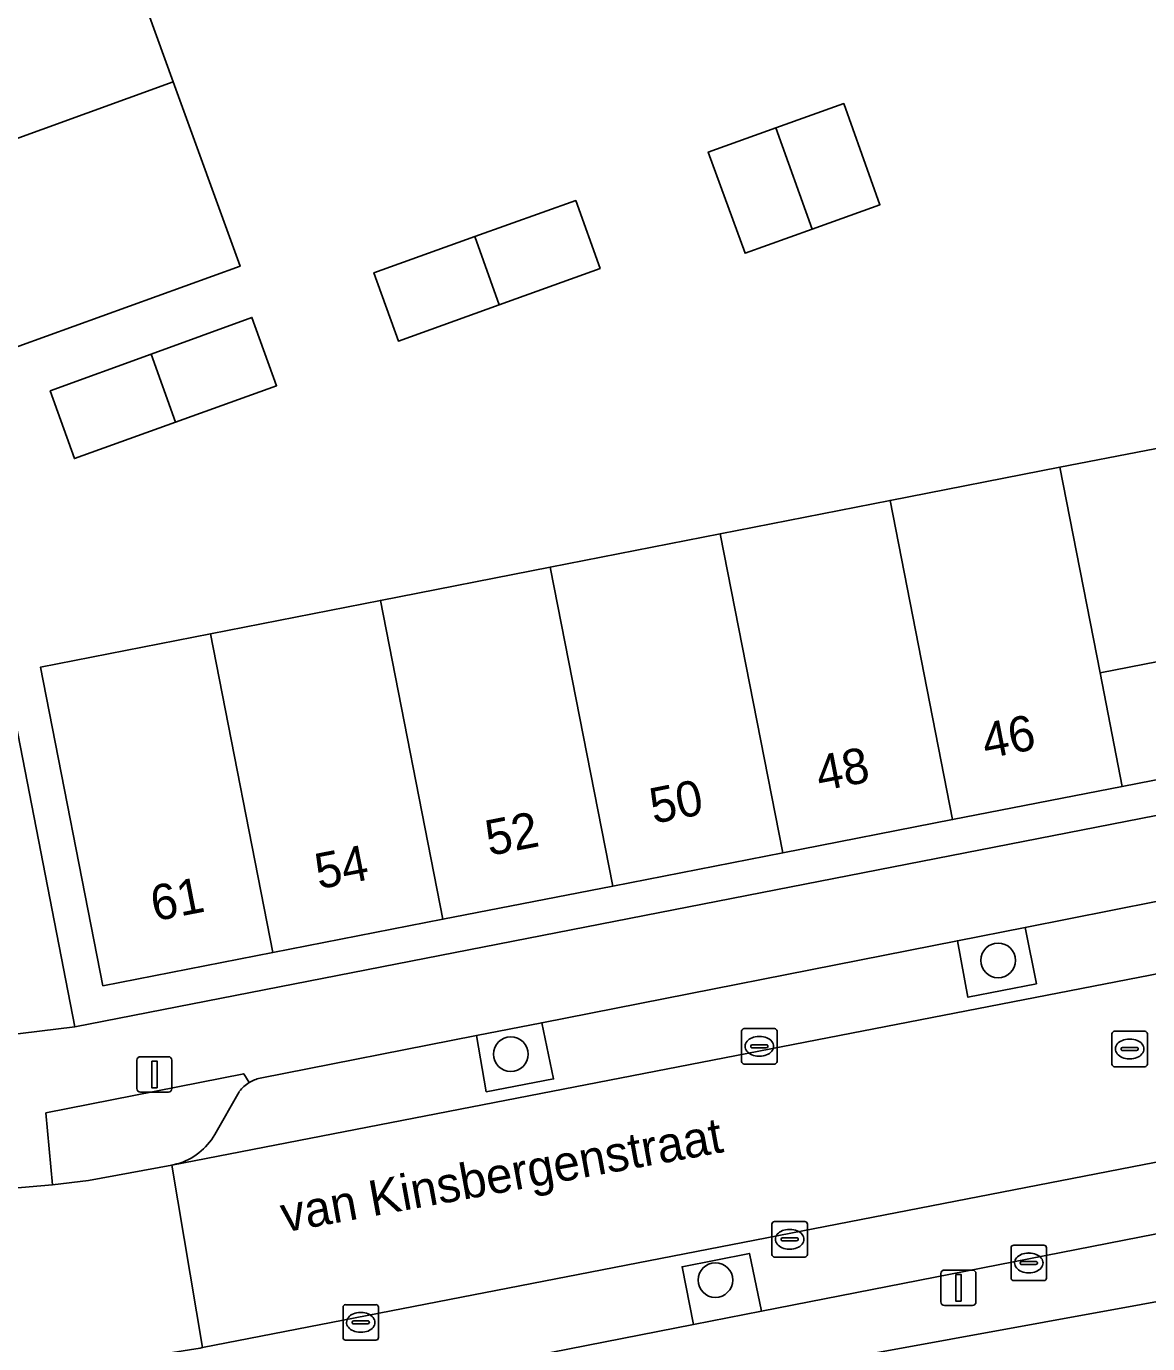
# Model space of a CAD drawing. Extents: x 160377 to 161131, y 383938 to 384853.
# Drawn here: x 160681.61 to 160713.26, y 384498.34 to 384535.5 of the extents above; entities that cross this region are included whole.
import ezdxf

# ---------------------------------------------------------------- set-up
doc = ezdxf.new("R2010")
doc.units = 0
for name, color, linetype in [('IMGEO_Boom', 7, 'Continuous'), ('IMGEO_Drainageput', 7, 'Continuous'), ('IMGEO_Erf', 7, 'Continuous'), ('IMGEO_Groenvoorziening', 7, 'Continuous'), ('IMGEO_Kolk', 7, 'Continuous'), ('IMGEO_Lichtmast', 7, 'Continuous'), ('IMGEO_Openbare_ruimte_label', 7, 'Continuous'), ('IMGEO_Pand', 7, 'Continuous'), ('IMGEO_Pand_nummerreeks', 7, 'Continuous'), ('IMGEO_Pand_overbouw', 7, 'Continuous'), ('IMGEO_Parkeervlak_open', 7, 'Continuous'), ('IMGEO_Rijbaan_lokaal_open', 7, 'Continuous'), ('IMGEO_Rioolput', 7, 'Continuous'), ('IMGEO_Voetgangersgebied_open', 7, 'Continuous'), ('IMGEO_Voetpad_open', 7, 'Continuous')]:
    doc.layers.add(name, color=color, linetype=linetype)

msp = doc.modelspace()

# ---------------------------------------------------------------- linework, layer by layer
at = {"layer": 'IMGEO_Boom'}
for centre in [(160709.037, 384509.154), (160695.282, 384506.508), (160701.057, 384500.136)]:
    msp.add_circle(centre, 0.489, dxfattribs=at)
at = {"layer": 'IMGEO_Drainageput'}
for p, q in [((160709.477, 384501.119), (160710.329, 384501.119)), ((160709.402, 384500.193), (160709.402, 384501.045)), ((160709.89, 384500.899), (160709.915, 384500.899)), ((160710.403, 384501.045), (160710.403, 384500.193)), ((160709.661, 384500.613), (160709.661, 384500.625)), ((160710.099, 384500.576), (160709.701, 384500.576)), ((160709.704, 384500.662), (160710.102, 384500.662)), ((160709.913, 384500.339), (160709.888, 384500.339)), ((160710.145, 384500.625), (160710.145, 384500.613)), ((160710.329, 384500.119), (160709.477, 384500.119))]:
    msp.add_line(p, q, dxfattribs=at)
for points in [[(160709.477, 384501.119), (160710.329, 384501.119)], [(160709.402, 384500.193), (160709.402, 384501.045)], [(160710.403, 384501.045), (160710.403, 384500.193)], [(160710.329, 384500.119), (160709.477, 384500.119)]]:
    msp.add_lwpolyline(points, dxfattribs=at)
for centre, radius, start, end in [((160709.479, 384501.043), 0.0765, 91.552, 178.448), ((160709.479, 384501.043), 0.0765, 91.552, 178.448), ((160710.327, 384501.043), 0.0765, 1.552, 88.448), ((160710.327, 384501.043), 0.0765, 1.552, 88.448), ((160709.701, 384500.622), 0.0403, 85.8775, 175.7526), ((160709.698, 384500.612), 0.0366, 178.938, 274.7102), ((160710.102, 384500.619), 0.043, 264.8664, 352.4533), ((160710.106, 384500.624), 0.0386, 1.7309, 96.639), ((160709.479, 384500.195), 0.0765, 181.552, 268.448), ((160709.479, 384500.195), 0.0765, 181.552, 268.448), ((160710.327, 384500.195), 0.0765, 271.552, 358.448), ((160710.327, 384500.195), 0.0765, 271.552, 358.448)]:
    msp.add_arc(centre, radius, start, end, dxfattribs=at)
for centre, major_axis, ratio, start_param, end_param in [((160709.889, 384500.619), (-0.387, 0.002), 0.722429, 4.712389, 7.853982), ((160709.914, 384500.619), (-0.39, 0.002), 0.717154, 1.570796, 4.712389)]:
    msp.add_ellipse(centre, major_axis=major_axis, ratio=ratio, start_param=start_param, end_param=end_param, dxfattribs=at)
at = {"layer": 'IMGEO_Erf'}
for points in [[(160742.043, 384557.929), (160741.675, 384559.771), (160712.316, 384578.736), (160711.06, 384579.547), (160690.284, 384592.968), (160678.608, 384600.475), (160670.645, 384605.594), (160652.047, 384589.687), (160648.865, 384586.974), (160652.625, 384581.692), (160662.829, 384567.417), (160665.29, 384560.709), (160670.064, 384547.52), (160670.583, 384546.086), (160681.057, 384517.15), (160682.984, 384507.279), (160717.593, 384514.044), (160723.481, 384515.195), (160749.399, 384520.262)], [(160683.874, 384539.137), (160685.758, 384533.937), (160687.643, 384528.737), (160679.045, 384525.635), (160677.165, 384530.822), (160675.28, 384536.022), (160673.396, 384541.222), (160671.511, 384546.422), (160680.104, 384549.537), (160681.989, 384544.337)], [(160702.767, 384532.64), (160704.679, 384533.323), (160705.699, 384530.47), (160703.788, 384529.782), (160701.895, 384529.1), (160700.854, 384531.956)], [(160694.269, 384529.57), (160697.117, 384530.589), (160697.802, 384528.674), (160694.956, 384527.649), (160692.111, 384526.624), (160691.421, 384528.551)], [(160685.13, 384526.254), (160687.977, 384527.293), (160688.674, 384525.363), (160685.821, 384524.336), (160682.968, 384523.309), (160682.287, 384525.217)], [(160691.603, 384519.309), (160696.398, 384520.249), (160701.193, 384521.188), (160705.987, 384522.128), (160710.782, 384523.068), (160711.912, 384517.267), (160716.78, 384518.215), (160717.444, 384514.809), (160717.025, 384514.727), (160716.963, 384514.925), (160712.537, 384514.06), (160707.752, 384513.125), (160702.957, 384512.188), (160698.162, 384511.251), (160693.366, 384510.314), (160688.571, 384509.377), (160683.77, 384508.439), (160682.014, 384517.429), (160686.809, 384518.369)], [(160733.41, 384501.572), (160743.969, 384503.506), (160744.111, 384503.532), (160747.441, 384504.142), (160747.616, 384504.174), (160749.48, 384504.514), (160748.356, 384505.867), (160702.23, 384497.471), (160702.513, 384495.915), (160711.376, 384497.537), (160716.884, 384498.546), (160722.393, 384499.555), (160727.901, 384500.564)]]:
    msp.add_lwpolyline(points, close=True, dxfattribs=at)
at = {"layer": 'IMGEO_Groenvoorziening'}
for points in [[(160709.802, 384510.082), (160707.889, 384509.705), (160708.183, 384508.112), (160710.119, 384508.492)], [(160696.156, 384507.393), (160694.314, 384507.03), (160694.589, 384505.449), (160696.493, 384505.812)], [(160700.435, 384498.879), (160702.355, 384499.255), (160702.017, 384500.885), (160700.119, 384500.512)]]:
    msp.add_lwpolyline(points, close=True, dxfattribs=at)
for points in [[(160687.9, 384505.71), (160687.745, 384505.957), (160682.165, 384504.852), (160682.351, 384502.826), (160683.364, 384502.943), (160685.714, 384503.375), (160685.86, 384503.41)], [(160686.931, 384504.242), (160687.622, 384505.45)]]:
    msp.add_lwpolyline(points, dxfattribs=at)
for centre, radius, start, end in [((160688.402, 384504.895), 0.958, 121.619, 144.5485), ((160685.365, 384505.153), 1.812, 285.8637, 329.8195)]:
    msp.add_arc(centre, radius, start, end, dxfattribs=at)
at = {"layer": 'IMGEO_Kolk'}
for p, q in [((160701.797, 384506.304), (160701.797, 384507.156)), ((160701.872, 384507.23), (160702.724, 384507.23)), ((160702.798, 384507.156), (160702.798, 384506.304)), ((160702.056, 384506.724), (160702.056, 384506.736)), ((160702.494, 384506.687), (160702.096, 384506.687)), ((160702.099, 384506.773), (160702.497, 384506.773)), ((160702.285, 384507.01), (160702.31, 384507.01)), ((160702.54, 384506.736), (160702.54, 384506.724)), ((160702.308, 384506.45), (160702.283, 384506.45)), ((160702.724, 384506.23), (160701.872, 384506.23)), ((160702.653, 384500.86), (160702.653, 384501.712)), ((160702.728, 384501.786), (160703.58, 384501.786)), ((160703.141, 384501.566), (160703.166, 384501.566)), ((160703.654, 384501.712), (160703.654, 384500.86)), ((160702.912, 384501.28), (160702.912, 384501.292)), ((160703.35, 384501.243), (160702.952, 384501.243)), ((160702.955, 384501.329), (160703.353, 384501.329)), ((160703.396, 384501.292), (160703.396, 384501.28)), ((160703.58, 384500.786), (160702.728, 384500.786)), ((160703.164, 384501.006), (160703.139, 384501.006)), ((160690.548, 384498.515), (160690.548, 384499.367)), ((160690.623, 384499.441), (160691.475, 384499.441)), ((160691.036, 384499.221), (160691.061, 384499.221)), ((160691.549, 384499.367), (160691.549, 384498.515)), ((160690.807, 384498.935), (160690.807, 384498.947)), ((160691.245, 384498.898), (160690.847, 384498.898)), ((160690.85, 384498.984), (160691.248, 384498.984)), ((160691.291, 384498.947), (160691.291, 384498.935)), ((160691.059, 384498.661), (160691.034, 384498.661)), ((160691.475, 384498.441), (160690.623, 384498.441))]:
    msp.add_line(p, q, dxfattribs=at)
for points in [[(160701.797, 384506.304), (160701.797, 384507.156)], [(160701.872, 384507.23), (160702.724, 384507.23)], [(160702.798, 384507.156), (160702.798, 384506.304)], [(160702.724, 384506.23), (160701.872, 384506.23)], [(160702.653, 384500.86), (160702.653, 384501.712)], [(160702.728, 384501.786), (160703.58, 384501.786)], [(160703.654, 384501.712), (160703.654, 384500.86)], [(160703.58, 384500.786), (160702.728, 384500.786)], [(160690.548, 384498.515), (160690.548, 384499.367)], [(160690.623, 384499.441), (160691.475, 384499.441)], [(160691.549, 384499.367), (160691.549, 384498.515)], [(160691.475, 384498.441), (160690.623, 384498.441)]]:
    msp.add_lwpolyline(points, dxfattribs=at)
for centre, radius, start, end in [((160701.874, 384507.154), 0.0765, 91.552, 178.448), ((160701.874, 384507.154), 0.0765, 91.552, 178.448), ((160702.722, 384507.154), 0.0765, 1.552, 88.448), ((160702.722, 384507.154), 0.0765, 1.552, 88.448), ((160702.096, 384506.733), 0.0403, 85.8775, 175.7526), ((160702.093, 384506.723), 0.0366, 178.938, 274.7102), ((160702.497, 384506.73), 0.043, 264.8664, 352.4533), ((160702.501, 384506.735), 0.0386, 1.7309, 96.639), ((160701.874, 384506.306), 0.0765, 181.552, 268.448), ((160701.874, 384506.306), 0.0765, 181.552, 268.448), ((160702.722, 384506.306), 0.0765, 271.552, 358.448), ((160702.722, 384506.306), 0.0765, 271.552, 358.448), ((160702.73, 384501.71), 0.0765, 91.552, 178.448), ((160702.73, 384501.71), 0.0765, 91.552, 178.448), ((160703.578, 384501.71), 0.0765, 1.552, 88.448), ((160703.578, 384501.71), 0.0765, 1.552, 88.448), ((160702.952, 384501.289), 0.0403, 85.8775, 175.7526), ((160702.949, 384501.279), 0.0366, 178.938, 274.7102), ((160703.353, 384501.286), 0.043, 264.8664, 352.4533), ((160703.357, 384501.291), 0.0386, 1.7309, 96.639), ((160702.73, 384500.862), 0.0765, 181.552, 268.448), ((160702.73, 384500.862), 0.0765, 181.552, 268.448), ((160703.578, 384500.862), 0.0765, 271.552, 358.448), ((160703.578, 384500.862), 0.0765, 271.552, 358.448), ((160690.625, 384499.365), 0.0765, 91.552, 178.448), ((160690.625, 384499.365), 0.0765, 91.552, 178.448), ((160691.473, 384499.365), 0.0765, 1.552, 88.448), ((160691.473, 384499.365), 0.0765, 1.552, 88.448), ((160690.847, 384498.944), 0.0403, 85.8775, 175.7526), ((160690.844, 384498.934), 0.0366, 178.938, 274.7102), ((160691.248, 384498.941), 0.043, 264.8664, 352.4533), ((160691.252, 384498.946), 0.0386, 1.7309, 96.639), ((160690.625, 384498.517), 0.0765, 181.552, 268.448), ((160690.625, 384498.517), 0.0765, 181.552, 268.448), ((160691.473, 384498.517), 0.0765, 271.552, 358.448), ((160691.473, 384498.517), 0.0765, 271.552, 358.448)]:
    msp.add_arc(centre, radius, start, end, dxfattribs=at)
for centre, major_axis, ratio, start_param, end_param in [((160702.284, 384506.73), (-0.387, 0.002), 0.722429, 4.712389, 7.853982), ((160702.309, 384506.73), (-0.39, 0.002), 0.717154, 1.570796, 4.712389), ((160703.14, 384501.286), (-0.387, 0.002), 0.722429, 4.712389, 7.853982), ((160703.165, 384501.286), (-0.39, 0.002), 0.717154, 1.570796, 4.712389), ((160691.035, 384498.941), (-0.387, 0.002), 0.722429, 4.712389, 7.853982), ((160691.06, 384498.941), (-0.39, 0.002), 0.717154, 1.570796, 4.712389)]:
    msp.add_ellipse(centre, major_axis=major_axis, ratio=ratio, start_param=start_param, end_param=end_param, dxfattribs=at)
at = {"layer": 'IMGEO_Lichtmast'}
for p, q in [((160684.73, 384505.537), (160684.73, 384506.337)), ((160684.73, 384506.337), (160684.73, 384505.537)), ((160684.83, 384506.437), (160685.62, 384506.437)), ((160685.62, 384506.437), (160684.83, 384506.437)), ((160685.72, 384506.337), (160685.72, 384505.537)), ((160685.72, 384505.537), (160685.72, 384506.337)), ((160685.62, 384505.437), (160684.83, 384505.437)), ((160684.83, 384505.437), (160685.62, 384505.437)), ((160707.521, 384500.418), (160708.311, 384500.418)), ((160708.311, 384500.418), (160707.521, 384500.418)), ((160707.421, 384499.518), (160707.421, 384500.318)), ((160707.421, 384500.318), (160707.421, 384499.518)), ((160708.411, 384500.318), (160708.411, 384499.518)), ((160708.411, 384499.518), (160708.411, 384500.318)), ((160708.311, 384499.418), (160707.521, 384499.418)), ((160707.521, 384499.418), (160708.311, 384499.418))]:
    msp.add_line(p, q, dxfattribs=at)
for points in [[(160685.15, 384506.312), (160685.3, 384506.312), (160685.3, 384505.562), (160685.15, 384505.562), (160685.15, 384506.312)], [(160707.841, 384500.293), (160707.991, 384500.293), (160707.991, 384499.543), (160707.841, 384499.543), (160707.841, 384500.293)]]:
    msp.add_lwpolyline(points, dxfattribs=at)
for centre, start, end in [((160684.83, 384506.337), 90, 180), ((160684.83, 384506.337), 90, 180), ((160685.62, 384506.337), 0, 90), ((160685.62, 384506.337), 360, 90), ((160684.83, 384505.537), 180, 270), ((160684.83, 384505.537), 180, 270), ((160685.62, 384505.537), 270, 0), ((160685.62, 384505.537), 270, 0), ((160707.521, 384500.318), 90, 180), ((160707.521, 384500.318), 90, 180), ((160708.311, 384500.318), 0, 90), ((160708.311, 384500.318), 360, 90), ((160707.521, 384499.518), 180, 270), ((160707.521, 384499.518), 180, 270), ((160708.311, 384499.518), 270, 0), ((160708.311, 384499.518), 270, 0)]:
    msp.add_arc(centre, 0.1, start, end, dxfattribs=at)
at = {"layer": 'IMGEO_Pand'}
for points in [[(160683.874, 384539.137), (160675.28, 384536.022), (160677.165, 384530.822), (160685.758, 384533.937)], [(160685.758, 384533.937), (160677.165, 384530.822), (160679.045, 384525.635), (160687.643, 384528.737)], [(160704.679, 384533.323), (160702.767, 384532.64), (160703.788, 384529.782), (160705.699, 384530.47)], [(160702.767, 384532.64), (160700.854, 384531.956), (160701.895, 384529.1), (160703.788, 384529.782)], [(160697.117, 384530.589), (160694.269, 384529.57), (160694.956, 384527.649), (160697.802, 384528.674)], [(160694.269, 384529.57), (160691.421, 384528.551), (160692.111, 384526.624), (160694.956, 384527.649)], [(160685.13, 384526.254), (160685.821, 384524.336), (160688.674, 384525.363), (160687.977, 384527.293)], [(160685.13, 384526.254), (160682.287, 384525.217), (160682.968, 384523.309), (160685.821, 384524.336)], [(160710.782, 384523.068), (160705.987, 384522.128), (160707.752, 384513.125), (160712.537, 384514.06), (160711.912, 384517.267)], [(160705.987, 384522.128), (160701.193, 384521.188), (160702.957, 384512.188), (160707.752, 384513.125)], [(160701.193, 384521.188), (160696.398, 384520.249), (160698.162, 384511.251), (160702.957, 384512.188)], [(160696.398, 384520.249), (160691.603, 384519.309), (160693.366, 384510.314), (160698.162, 384511.251)], [(160691.603, 384519.309), (160686.809, 384518.369), (160688.571, 384509.377), (160693.366, 384510.314)], [(160686.809, 384518.369), (160682.014, 384517.429), (160683.77, 384508.439), (160688.571, 384509.377)], [(160716.78, 384518.215), (160711.912, 384517.267), (160712.537, 384514.06), (160716.963, 384514.925), (160717.025, 384514.727), (160717.444, 384514.809)]]:
    msp.add_lwpolyline(points, close=True, dxfattribs=at)
at = {"layer": 'IMGEO_Pand_overbouw'}
msp.add_lwpolyline([(160718.925, 384522.896), (160715.98, 384522.325), (160715.65, 384524.011), (160710.782, 384523.068), (160711.912, 384517.267), (160716.78, 384518.215), (160717.444, 384514.809), (160720.382, 384515.381)], close=True, dxfattribs=at)
at = {"layer": 'IMGEO_Parkeervlak_open'}
for points in [[(160713.495, 384510.81), (160709.802, 384510.082), (160710.119, 384508.492), (160708.183, 384508.112), (160707.889, 384509.705), (160696.156, 384507.393), (160696.493, 384505.812), (160694.589, 384505.449), (160694.314, 384507.03), (160688.207, 384505.827)], [(160685.86, 384503.41), (160685.714, 384503.375), (160716.914, 384509.435)], [(160743.994, 384509.389), (160686.58, 384498.232), (160686.513, 384498.219)], [(160687.622, 384505.45), (160686.931, 384504.242)], [(160689.896, 384496.817), (160700.435, 384498.879), (160700.119, 384500.512), (160702.017, 384500.885), (160702.355, 384499.255), (160724.13, 384503.516)]]:
    msp.add_lwpolyline(points, dxfattribs=at)
for centre, radius, start, end in [((160688.402, 384504.895), 0.958, 121.619, 144.5485), ((160688.379, 384504.914), 0.929, 100.6812, 121.0432), ((160685.365, 384505.153), 1.812, 285.8637, 329.8195)]:
    msp.add_arc(centre, radius, start, end, dxfattribs=at)
at = {"layer": 'IMGEO_Rijbaan_lokaal_open'}
msp.add_lwpolyline([(160743.994, 384509.389), (160744.156, 384509.432), (160744.272, 384509.456), (160743.248, 384514.579), (160725.821, 384511.164), (160716.914, 384509.435), (160685.714, 384503.375), (160686.58, 384498.232)], close=True, dxfattribs=at)
msp.add_lwpolyline([(160681.08, 384497.44), (160684.957, 384497.974), (160686.513, 384498.219), (160686.58, 384498.232), (160685.714, 384503.375), (160683.364, 384502.943), (160682.351, 384502.826), (160681.144, 384502.714), (160666.223, 384501.382), (160656.868, 384500.475), (160656.011, 384500.414), (160656.518, 384494.884), (160658.107, 384495.062), (160660.061, 384495.216)], dxfattribs=at)
at = {"layer": 'IMGEO_Rioolput'}
for p, q in [((160712.248, 384506.229), (160712.248, 384507.081)), ((160712.323, 384507.155), (160713.175, 384507.155)), ((160713.249, 384507.081), (160713.249, 384506.229)), ((160712.507, 384506.649), (160712.507, 384506.661)), ((160712.55, 384506.698), (160712.948, 384506.698)), ((160712.736, 384506.935), (160712.761, 384506.935)), ((160712.991, 384506.661), (160712.991, 384506.649)), ((160712.945, 384506.612), (160712.547, 384506.612)), ((160712.759, 384506.375), (160712.734, 384506.375)), ((160713.175, 384506.155), (160712.323, 384506.155))]:
    msp.add_line(p, q, dxfattribs=at)
for points in [[(160712.248, 384506.229), (160712.248, 384507.081)], [(160712.323, 384507.155), (160713.175, 384507.155)], [(160713.249, 384507.081), (160713.249, 384506.229)], [(160713.175, 384506.155), (160712.323, 384506.155)]]:
    msp.add_lwpolyline(points, dxfattribs=at)
for centre, radius, start, end in [((160712.325, 384507.079), 0.0765, 91.552, 178.448), ((160712.325, 384507.079), 0.0765, 91.552, 178.448), ((160713.173, 384507.079), 0.0765, 1.552, 88.448), ((160713.173, 384507.079), 0.0765, 1.552, 88.448), ((160712.547, 384506.658), 0.0403, 85.8775, 175.7526), ((160712.544, 384506.648), 0.0366, 178.938, 274.7102), ((160712.948, 384506.655), 0.043, 264.8664, 352.4533), ((160712.952, 384506.66), 0.0386, 1.7309, 96.639), ((160712.325, 384506.231), 0.0765, 181.552, 268.448), ((160712.325, 384506.231), 0.0765, 181.552, 268.448), ((160713.173, 384506.231), 0.0765, 271.552, 358.448), ((160713.173, 384506.231), 0.0765, 271.552, 358.448)]:
    msp.add_arc(centre, radius, start, end, dxfattribs=at)
for centre, major_axis, ratio, start_param, end_param in [((160712.735, 384506.655), (-0.387, 0.002), 0.722429, 4.712389, 7.853982), ((160712.76, 384506.655), (-0.39, 0.002), 0.717154, 1.570796, 4.712389)]:
    msp.add_ellipse(centre, major_axis=major_axis, ratio=ratio, start_param=start_param, end_param=end_param, dxfattribs=at)
at = {"layer": 'IMGEO_Voetgangersgebied_open'}
msp.add_lwpolyline([(160676.497, 384522.259), (160678.548, 384514.302), (160680.437, 384506.971), (160682.984, 384507.279), (160681.057, 384517.15), (160670.583, 384546.086), (160670.064, 384547.52), (160665.29, 384560.709)], dxfattribs=at)
at = {"layer": 'IMGEO_Voetpad_open'}
for points in [[(160818.393, 384535.428), (160814.707, 384533.039), (160790.946, 384528.391), (160785.079, 384527.244), (160759.828, 384522.305), (160757.353, 384521.841), (160751.078, 384520.595), (160749.399, 384520.262), (160723.481, 384515.195), (160717.593, 384514.044), (160682.984, 384507.279), (160680.437, 384506.971), (160680.951, 384504.783), (160681.144, 384502.714), (160682.351, 384502.826), (160682.165, 384504.852), (160687.745, 384505.957), (160687.9, 384505.71)], [(160688.207, 384505.827), (160694.314, 384507.03), (160696.156, 384507.393), (160707.889, 384509.705), (160709.802, 384510.082), (160713.495, 384510.81)], [(160741.599, 384506.921), (160734.561, 384505.557), (160725.782, 384503.839), (160724.13, 384503.516), (160702.355, 384499.255), (160700.435, 384498.879), (160689.896, 384496.817)], [(160675.404, 384486.813), (160675.535, 384486.616), (160675.88, 384486.183), (160676.022, 384486.022), (160679.533, 384487.97), (160687.518, 384494.794), (160700.75, 384497.202), (160702.23, 384497.471), (160748.356, 384505.867)]]:
    msp.add_lwpolyline(points, dxfattribs=at)
msp.add_arc((160688.379, 384504.914), 0.929, 100.6812, 121.0432, dxfattribs=at)

# ---------------------------------------------------------------- texts
at = {"layer": 'IMGEO_Openbare_ruimte_label'}
msp.add_text('van Kinsbergenstraat', height=1, rotation=10.3663, dxfattribs=at).set_placement((160688.89, 384501.477))
at = {"layer": 'IMGEO_Pand_nummerreeks'}
for s, p in [('46', (160708.69, 384514.836)), ('48', (160704.005, 384513.921)), ('50', (160699.311, 384513.004)), ('52', (160694.674, 384512.098)), ('54', (160689.865, 384511.158)), ('61', (160685.23, 384510.252))]:
    msp.add_text(s, height=1, rotation=11.0581, dxfattribs=at).set_placement(p)

doc.saveas('drawing.dxf')
